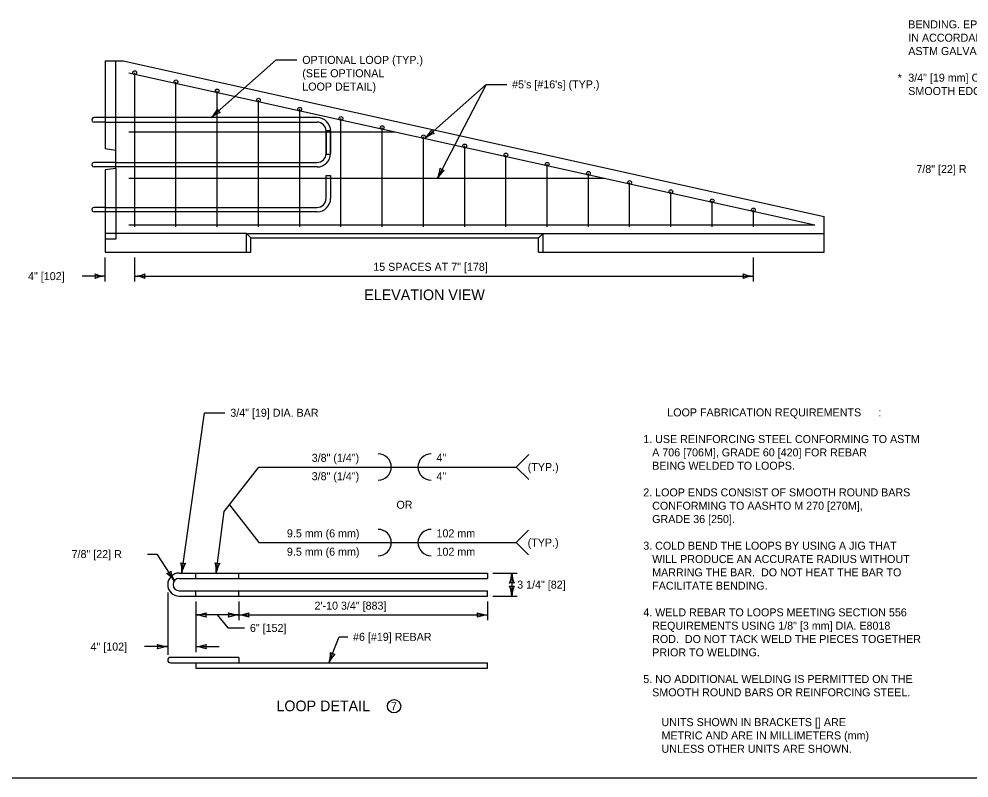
# Model space of a CAD drawing. Extents: x 49991.4 to 50021, y 49987.6 to 50011.4.
# Drawn here: x 50006.04 to 50013.16, y 49987.8 to 49993.49 of the extents above; entities that cross this region are included whole.
import ezdxf

# ---------------------------------------------------------------- set-up
doc = ezdxf.new("R2010")
doc.units = 0
for name, color, linetype in [('Level 1', 7, 'Continuous'), ('Level 2', 7, 'Continuous'), ('Level 3', 7, 'Continuous'), ('Level 4', 7, 'Continuous')]:
    doc.layers.add(name, color=color, linetype=linetype)

msp = doc.modelspace()

# ---------------------------------------------------------------- linework, layer by layer
at = {"layer": 'Level 1'}
for p, q in [((50006.6822, 49993.18), (50006.8169, 49993.18)), ((50006.6822, 49993.18), (50006.6822, 49992.5185)), ((50006.8169, 49993.18), (50012.0708, 49992.0123)), ((50006.8599, 49993.0901), (50012.0019, 49991.9478)), ((50006.903, 49991.9341), (50006.903, 49993.09)), ((50007.2122, 49991.9341), (50007.2122, 49993.0216)), ((50007.5214, 49991.9341), (50007.5214, 49992.9529)), ((50007.8306, 49991.9341), (50007.8306, 49992.8842)), ((50008.1398, 49991.9341), (50008.1398, 49992.8155)), ((50006.6822, 49992.7527), (50006.5983, 49992.7526)), ((50006.6822, 49992.719), (50006.5983, 49992.719)), ((50008.449, 49991.9341), (50008.449, 49992.7468)), ((50006.8589, 49992.6474), (50008.8525, 49992.6474)), ((50008.7581, 49991.9341), (50008.7581, 49992.6781)), ((50009.0673, 49991.9341), (50009.0673, 49992.6095)), ((50006.7607, 49992.5065), (50006.6822, 49992.5185)), ((50006.7608, 49992.372), (50006.7607, 49992.5065)), ((50009.3765, 49991.9341), (50009.3765, 49992.5408)), ((50009.3765, 49991.9341), (50009.3765, 49992.5403)), ((50009.6857, 49991.9341), (50009.6857, 49992.4721)), ((50006.7608, 49992.4163), (50006.5983, 49992.4164)), ((50006.7608, 49992.3826), (50006.5983, 49992.3828)), ((50006.7608, 49992.372), (50006.6822, 49992.3602)), ((50006.6822, 49992.3602), (50006.6822, 49991.7429)), ((50009.9949, 49991.9341), (50009.9949, 49992.4034)), ((50006.8589, 49992.2976), (50010.4272, 49992.2976)), ((50010.304, 49991.9341), (50010.304, 49992.3347)), ((50010.6132, 49991.9341), (50010.6132, 49992.266)), ((50010.9224, 49991.9341), (50010.9224, 49992.1973)), ((50006.6822, 49992.0796), (50006.5983, 49992.0796)), ((50011.2316, 49991.9341), (50011.2316, 49992.1287)), ((50006.6822, 49992.0459), (50006.5983, 49992.046)), ((50011.5408, 49991.9341), (50011.5408, 49992.06)), ((50012.0708, 49991.743), (50012.0708, 49992.0123)), ((50006.8589, 49991.9478), (50012.0019, 49991.9478)), ((50007.7406, 49991.7429), (50007.7406, 49991.8843)), ((50007.7406, 49991.8843), (50007.7742, 49991.8508)), ((50007.7406, 49991.8843), (50009.9636, 49991.8843)), ((50007.7742, 49991.7429), (50007.7742, 49991.8508)), ((50007.7742, 49991.8508), (50009.9296, 49991.8508)), ((50009.9296, 49991.8508), (50009.9636, 49991.8843)), ((50009.9296, 49991.743), (50009.9296, 49991.8508)), ((50009.9636, 49991.743), (50009.9636, 49991.8843)), ((50006.6822, 49991.7429), (50007.7742, 49991.7429)), ((50009.9296, 49991.743), (50012.0708, 49991.743)), ((50007.237, 49989.3361), (50009.5477, 49989.3363)), ((50007.237, 49989.296), (50009.5477, 49989.2963)), ((50007.6829, 49989.2961), (50007.6829, 49989.3362)), ((50009.5477, 49989.3363), (50009.5477, 49989.2963)), ((50007.237, 49989.2031), (50009.5477, 49989.2033)), ((50007.237, 49989.163), (50009.5477, 49989.1631)), ((50007.6829, 49989.163), (50007.6829, 49989.2031)), ((50009.5477, 49989.1631), (50009.5477, 49989.2033)), ((50007.6829, 49988.7034), (50007.1705, 49988.7031)), ((50007.1705, 49988.663), (50009.5477, 49988.6632)), ((50007.3618, 49988.663), (50007.3618, 49988.6231)), ((50007.6829, 49988.7034), (50007.6829, 49988.663)), ((50009.5477, 49988.6231), (50009.5477, 49988.6632)), ((50007.3618, 49988.6231), (50009.5477, 49988.6231))]:
    msp.add_line(p, q, dxfattribs=at)
msp.add_lwpolyline([(49999.3835, 49998.9992), (50016.7501, 49998.9992), (50016.7501, 49987.7988), (49999.3835, 49987.7988)], close=True, dxfattribs=at)
for centre, radius in [((50007.237, 49989.2496), 0.0866), ((50007.237, 49989.2496), 0.0465), ((50007.1705, 49988.6831), 0.0201)]:
    msp.add_arc(centre, radius, 90, 270, dxfattribs=at)
for centre in [(50006.903, 49993.09), (50007.2122, 49993.0216), (50007.5214, 49992.9529), (50007.8306, 49992.8842), (50008.1398, 49992.8155), (50008.449, 49992.7468), (50008.7581, 49992.6781), (50009.0673, 49992.6095), (50009.3765, 49992.5403), (50009.6857, 49992.4721), (50009.9949, 49992.4034), (50010.304, 49992.3347), (50010.6132, 49992.266), (50010.9224, 49992.1973), (50011.2316, 49992.1287), (50011.5408, 49992.06)]:
    msp.add_ellipse(centre, major_axis=(0.014, 0), ratio=0.999993, dxfattribs=at)
for centre in [(50006.5983, 49992.7358), (50006.5983, 49992.3996), (50006.5983, 49992.0628)]:
    msp.add_ellipse(centre, major_axis=(0.0168, 0), ratio=0.999993, start_param=1.570796, end_param=4.712389, dxfattribs=at)
at = {"layer": 'Level 2'}
msp.add_ellipse((50008.8471, 49988.3369), major_axis=(0.05, 0), ratio=0.9994, dxfattribs=at)
at = {"layer": 'Level 3'}
for p, q in [((50007.4764, 49992.7527), (50007.9644, 49993.1858)), ((50007.9644, 49993.1858), (50008.1191, 49993.1858)), ((50009.0803, 49992.5968), (50009.5371, 49993.0024)), ((50009.5371, 49993.0024), (50009.1725, 49992.2976)), ((50009.5371, 49993.0024), (50009.6919, 49993.0024)), ((50006.6822, 49991.5236), (50006.6822, 49991.7029)), ((50006.903, 49991.5236), (50006.903, 49991.7029)), ((50011.5411, 49991.5236), (50011.5411, 49991.703)), ((50006.6822, 49991.5636), (50006.5088, 49991.5636)), ((50006.903, 49991.5636), (50011.5411, 49991.5636)), ((50007.2555, 49989.3363), (50007.4272, 49990.5388)), ((50007.4272, 49990.5388), (50007.5796, 49990.5388)), ((50009.7628, 49990.1317), (50009.8562, 49990.2251)), ((50007.5738, 49989.7974), (50007.8331, 49990.1319)), ((50007.8331, 49990.1319), (50009.7628, 49990.1319)), ((50009.7628, 49990.1317), (50009.8562, 49990.0385)), ((50007.6135, 49989.8486), (50007.8331, 49989.5652)), ((50009.7623, 49989.5652), (50009.8557, 49989.6586)), ((50007.8331, 49989.5652), (50009.7623, 49989.5652)), ((50009.7623, 49989.5652), (50009.8557, 49989.472)), ((50006.9984, 49989.4787), (50007.0697, 49989.4787)), ((50007.0696, 49989.4787), (50007.1998, 49989.2774)), ((50009.5877, 49989.3363), (50009.7702, 49989.3363)), ((50009.7302, 49989.3363), (50009.7302, 49989.1631)), ((50007.1504, 49989.1896), (50007.1504, 49988.7231)), ((50009.5877, 49989.1631), (50009.7702, 49989.1631)), ((50007.3618, 49989.123), (50007.3617, 49988.7432)), ((50007.6828, 49989.123), (50007.6828, 49988.9817)), ((50009.5476, 49989.1231), (50009.5476, 49988.9817)), ((50007.6828, 49989.0217), (50007.3618, 49989.0217)), ((50007.6828, 49989.0217), (50009.5476, 49989.0217)), ((50007.1504, 49988.7842), (50006.977, 49988.7842)), ((50007.3617, 49988.7842), (50007.5351, 49988.7842))]:
    msp.add_line(p, q, dxfattribs=at)
for points in [[(50007.5137, 49989.3362), (50007.5738, 49989.7974)], [(50007.5223, 49989.0217), (50007.6013, 49988.9245), (50007.7266, 49988.9245)], [(50008.3593, 49988.6632), (50008.4345, 49988.8579), (50008.4995, 49988.8579)]]:
    msp.add_lwpolyline(points, dxfattribs=at)
for centre, radius, start, end in [((50007.3134, 49992.9191), 0.233, 314.42113, 333.67098), ((50007.6171, 49992.5805), 0.2223, 109.04983, 129.23334), ((50007.5723, 49992.8378), 0.0548, 203.73264, 239.455), ((50008.9172, 49992.7633), 0.233, 314.42113, 333.67098), ((50009.2209, 49992.4246), 0.2223, 109.04983, 129.23334), ((50009.1762, 49992.682), 0.0548, 203.73264, 239.455), ((50008.9605, 49992.3943), 0.233, 335.47232, 354.72217), ((50009.3656, 49992.1874), 0.2223, 130.10102, 150.28453), ((50009.2314, 49992.4115), 0.0548, 224.78383, 260.50619), ((50006.6914, 49991.7857), 0.2223, 247.45601, 267.63952), ((50006.554, 49991.5636), 0.0548, 342.13882, 17.86118), ((50006.6937, 49991.3309), 0.233, 92.82731, 112.07716), ((50006.8916, 49991.7963), 0.233, 272.82731, 292.07716), ((50006.8939, 49991.3414), 0.2223, 67.45601, 87.63952), ((50007.0313, 49991.5636), 0.0548, 162.13882, 197.86118), ((50011.5503, 49991.7857), 0.2223, 247.45601, 267.63952), ((50011.4129, 49991.5636), 0.0548, 342.13882, 17.86118), ((50011.5526, 49991.3309), 0.233, 92.82731, 112.07716), ((50008.7276, 49990.1319), 0.0989, 270, 90), ((50009.1254, 49990.1319), 0.0989, 90, 270), ((50008.7276, 49989.5652), 0.0989, 270, 90), ((50009.1254, 49989.5652), 0.0989, 90, 270), ((50007.2736, 49989.4633), 0.0548, 244.01002, 279.73238), ((50007.0235, 49989.3579), 0.233, 354.69851, 13.94836), ((50007.4741, 49989.2959), 0.2223, 149.32721, 169.51072), ((50007.5303, 49989.4633), 0.0548, 244.71032, 280.43268), ((50007.2814, 49989.3549), 0.233, 355.39881, 14.64866), ((50007.7328, 49989.2984), 0.2223, 150.02751, 170.21102), ((50007.1302, 49989.385), 0.0548, 285.05282, 320.77518), ((50007.0107, 49989.1413), 0.233, 35.74131, 54.99116), ((50007.3913, 49989.3904), 0.2223, 190.37001, 210.55352), ((50009.5081, 49989.3455), 0.2223, 337.45601, 357.63952), ((50009.9629, 49989.3478), 0.233, 182.82731, 202.07716), ((50009.7302, 49989.2081), 0.0548, 72.13882, 107.86118), ((50009.7302, 49989.2913), 0.0548, 252.13882, 287.86118), ((50009.4975, 49989.1516), 0.233, 2.82731, 22.07716), ((50009.9524, 49989.154), 0.2223, 157.45601, 177.63952), ((50007.3503, 49989.2544), 0.233, 272.82731, 292.07716), ((50007.3526, 49988.7996), 0.2223, 67.45601, 87.63952), ((50007.49, 49989.0217), 0.0548, 162.13882, 197.86118), ((50007.6919, 49989.2438), 0.2223, 247.45601, 267.63952), ((50007.5545, 49989.0217), 0.0548, 342.13882, 17.86118), ((50007.6942, 49988.789), 0.233, 92.82731, 112.07716), ((50007.6713, 49989.2544), 0.233, 272.82731, 292.07716), ((50007.6736, 49988.7996), 0.2223, 67.45601, 87.63952), ((50007.811, 49989.0217), 0.0548, 162.13882, 197.86118), ((50009.5568, 49989.2438), 0.2223, 247.45601, 267.63952), ((50009.4194, 49989.0217), 0.0548, 342.13882, 17.86118), ((50009.5591, 49988.789), 0.233, 92.82731, 112.07716), ((50007.1596, 49989.0063), 0.2223, 247.45601, 267.63952), ((50007.0222, 49988.7842), 0.0548, 342.13882, 17.86118), ((50007.3502, 49989.0169), 0.233, 272.82731, 292.07716), ((50007.49, 49988.7842), 0.0548, 162.13882, 197.86118), ((50007.1619, 49988.5515), 0.233, 92.82731, 112.07716), ((50007.3526, 49988.562), 0.2223, 67.45601, 87.63952), ((50008.1381, 49988.7362), 0.233, 341.72472, 0.97457), ((50008.5632, 49988.5746), 0.2223, 136.35342, 156.53693), ((50008.4055, 49988.7827), 0.0548, 231.03623, 266.75859)]:
    msp.add_arc(centre, radius, start, end, dxfattribs=at)
at = {"layer": 'Level 4'}
for p, q in [((50006.7607, 49992.5065), (50006.7607, 49993.18)), ((50008.2707, 49992.7527), (50006.6822, 49992.7527)), ((50006.6822, 49992.719), (50008.2707, 49992.719)), ((50008.3377, 49992.4836), (50008.3377, 49992.6556)), ((50008.3377, 49992.6556), (50008.3714, 49992.6556)), ((50008.3379, 49992.6518), (50008.3379, 49992.4797)), ((50008.3714, 49992.6556), (50008.3714, 49992.4836)), ((50008.3717, 49992.4797), (50008.3717, 49992.6518)), ((50008.3379, 49992.4797), (50008.3717, 49992.4797)), ((50006.7608, 49992.4163), (50008.2704, 49992.4163)), ((50008.2704, 49992.3826), (50006.7608, 49992.3826)), ((50006.7608, 49992.372), (50006.7608, 49991.8414)), ((50008.338, 49992.1468), (50008.338, 49992.3188)), ((50008.338, 49992.3188), (50008.3717, 49992.3188)), ((50008.3717, 49992.3188), (50008.3717, 49992.1468)), ((50006.6822, 49992.0796), (50008.2707, 49992.0795)), ((50008.2707, 49992.0459), (50006.6822, 49992.0459)), ((50007.7406, 49991.8843), (50006.6822, 49991.8842)), ((50009.9636, 49991.8843), (50012.0708, 49991.8842)), ((50006.7608, 49991.8414), (50006.6822, 49991.8414)), ((50007.3618, 49989.296), (50007.3618, 49989.3362)), ((50007.3618, 49989.163), (50007.3618, 49989.2031))]:
    msp.add_line(p, q, dxfattribs=at)
for centre, radius, start, end in [((50008.27, 49992.651), 0.1017, 0.43427, 89.60389), ((50008.2707, 49992.6518), 0.0672, 360, 90), ((50008.2704, 49992.4836), 0.0672, 270, 0), ((50008.2697, 49992.4843), 0.1017, 270.39611, 359.56573), ((50008.2707, 49992.1468), 0.0672, 270, 0), ((50008.27, 49992.1475), 0.1017, 270.39611, 359.56573)]:
    msp.add_arc(centre, radius, start, end, dxfattribs=at)

# ---------------------------------------------------------------- texts
at = {"layer": 'Level 2'}
for s, height, p in [('BENDING. EPOXY COAT IN ACCORDANCE WITH SUBSECTION 711.02.1. GALVANIZE', 0.06, (50012.7015, 49993.4224)), ('IN ACCORDANCE WITH ASTM A153, B695 (CLASS 50) OR OTHER APPLICABLE', 0.06, (50012.7015, 49993.3224)), ('ASTM GALVANIZING STANDARDS. ', 0.06, (50012.7015, 49993.2224)), ('OPTIONAL LOOP (TYP.)', 0.06, (50008.1591, 49993.1558)), ('(SEE OPTIONAL', 0.06, (50008.1591, 49993.0558)), ('*', 0.06, (50012.6217, 49993.0224)), ('3/4" [19 mm] CHAMFER ENTIRE OPENING (OR SUFFICIENTLY ROUNDED SO THAT A', 0.06, (50012.7015, 49993.0224)), ('LOOP DETAIL)', 0.06, (50008.1591, 49992.9558)), ("#5's [#16's] (TYP.)", 0.06, (50009.7319, 49992.9724)), ('SMOOTH EDGE RESULTS.) 1/2" [13 mm] CHAMFER IS ACCEPTABLE.  ', 0.06, (50012.7015, 49992.9224)), ('7/8" [22] R', 0.06, (50012.7624, 49992.3374)), ('15 SPACES AT 7" [178]', 0.06, (50008.6915, 49991.6036)), ('4" [102]', 0.06, (50006.1038, 49991.5336)), ('ELEVATION VIEW', 0.079997, (50008.6238, 49991.3836)), ('LOOP FABRICATION REQUIREMENTS', 0.06, (50010.8951, 49990.5115)), (':', 0.06, (50012.4778, 49990.5115)), ('1. USE REINFORCING STEEL CONFORMING TO ASTM ', 0.06, (50010.7151, 49990.3115)), ('3/8" (1/4")', 0.06, (50008.2298, 49990.1708)), ('4"', 0.06, (50009.1653, 49990.1719)), ('   A 706 [706M], GRADE 60 [420] FOR REBAR ', 0.06, (50010.7151, 49990.2115)), ('(TYP.)', 0.06, (50009.8491, 49990.1015)), ('   BEING WELDED TO LOOPS.', 0.06, (50010.7151, 49990.1115)), ('3/8" (1/4")', 0.06, (50008.2298, 49990.033)), ('4"', 0.06, (50009.1654, 49990.033)), ('2. LOOP ENDS CONSIST OF SMOOTH ROUND BARS ', 0.06, (50010.7151, 49989.9115)), ('OR', 0.06, (50008.8649, 49989.8186)), ('   CONFORMING TO AASHTO M 270 [270M], ', 0.06, (50010.7151, 49989.8115)), ('   GRADE 36 [250].', 0.06, (50010.7151, 49989.7115)), ('9.5 mm (6 mm)', 0.06, (50008.044, 49989.604)), ('102 mm', 0.06, (50009.1654, 49989.604)), ('(TYP.)', 0.06, (50009.8486, 49989.535)), ('3. COLD BEND THE LOOPS BY USING A JIG THAT ', 0.06, (50010.7151, 49989.5115)), (' 7/8" [22] R', 0.06, (50006.4077, 49989.4487)), ('9.5 mm (6 mm)', 0.06, (50008.044, 49989.4663)), ('102 mm', 0.06, (50009.1654, 49989.4663)), ('   WILL PRODUCE AN ACCURATE RADIUS WITHOUT ', 0.06, (50010.7151, 49989.4115)), ('   MARRING THE BAR.  DO NOT HEAT THE BAR TO ', 0.06, (50010.7151, 49989.3115)), ('3 1/4" [82]', 0.06, (50009.7702, 49989.2197)), ('   FACILITATE BENDING.', 0.06, (50010.7151, 49989.2115)), ('2\'-10 3/4" [883]', 0.06, (50008.2509, 49989.0617)), ('4. WELD REBAR TO LOOPS MEETING SECTION 556 ', 0.06, (50010.7151, 49989.0115)), ('6" [152]', 0.06, (50007.7666, 49988.8945)), ('   REQUIREMENTS USING 1/8" [3 mm] DIA. E8018 ', 0.06, (50010.7151, 49988.9115)), ('#6 [#19] REBAR', 0.06, (50008.5395, 49988.8279)), ('   ROD.  DO NOT TACK WELD THE PIECES TOGETHER ', 0.06, (50010.7151, 49988.8115)), ('4" [102]', 0.06, (50006.572, 49988.7542)), ('   PRIOR TO WELDING.', 0.06, (50010.7151, 49988.7115)), ('5. NO ADDITIONAL WELDING IS PERMITTED ON THE ', 0.06, (50010.7151, 49988.5115)), ('   SMOOTH ROUND BARS OR REINFORCING STEEL.', 0.06, (50010.7151, 49988.4115)), ('LOOP DETAIL', 0.08, (50007.9654, 49988.2999)), ('7', 0.06, (50008.8233, 49988.3069)), ('UNITS SHOWN IN BRACKETS [] ARE ', 0.06, (50010.8519, 49988.1881)), ('METRIC AND ARE IN MILLIMETERS (mm) ', 0.06, (50010.8519, 49988.0881)), ('UNLESS OTHER UNITS ARE SHOWN.', 0.06, (50010.8519, 49987.9881))]:
    msp.add_text(s, height=height, dxfattribs=at).set_placement(p)
msp.add_text('3/4" [19] DIA. BAR', height=0.06, rotation=360, dxfattribs=at).set_placement((50007.6196, 49990.5088))

doc.saveas('drawing.dxf')
